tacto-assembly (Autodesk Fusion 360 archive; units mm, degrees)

design "smart-kitchen-timer" references "3.7v li-ion 500mah Battery", "Micro_Button_6x6", "XIAO-nRF52840 v15", "HW-040 Encoder module", "Wavehsare 1.54in e-paper - Module"
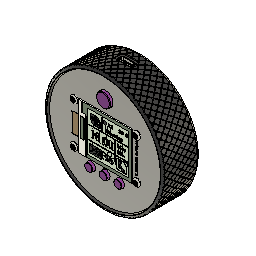
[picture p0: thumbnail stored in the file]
part number: 2025-10-14-07-23-40-648
part number: 2025-10-14-07-30-10-899
part number: 2025-10-14-07-51-40-944
part number: 2025-10-14-07-53-39-691
part number: 2025-10-14-09-25-19-943
part number: 2025-10-14-09-45-08-360
sketch "Skizze1" plane through (0, 0, 0) normal (0, 1, 0) x axis (1, 0, 0)
  circle C1 centre (0, 0) radius 40
  point P1 (0, 0)
  point P2 (0, 0)
  coincident P1 P2
  dimension "d1" diameter C1 = 80
component_insert "Komponente einfügen1"
component_insert "Komponente einfügen1"
sketch "Skizze2" plane through (0, 0, 0) normal (1, 0, 0) x axis (0, 1, 0)
  line L1 (23, 41) -> (-2, 41)
  line L2 (23, 39) -> (23, 41)
  line L3 (-2, 39) -> (23, 39)
  line L4 (-2, 41) -> (-2, 39)
  point P6 (0, 0)
  horizontal L1
  vertical L2
  horizontal L3
  vertical L4
  dimension "d2" distance L4 P6 = 2
  dimension "d3" distance L1 L3 = 2
  dimension "d4" distance L2 L4 = 25
  dimension "d5" distance L3 P6 = 39 (= "( 78 / 2 ) * 1 mm")
revolve "Drehen1" sketch "Skizze2" AlongAngle 360
sketch "Skizze3" plane through (0, 23, 0) normal (0, 1, 0) x axis (-1, 0, 0)
  circle C1 centre (0, 0) radius 41
  circle C2 centre (0, 0) radius 39
position "Position1"
copy_paste "Kopieren/Einfügen1"
copy_paste "Kopieren/Einfügen2"
position "Position2"
sketch "Skizze4" plane through (0, 0, 0) normal (0, -1, 0) x axis (1, 0, 0)
  line L1 (-24.0928, 9.2469) -> (-24.0928, 13.5382)
  line L2 (-22.6392, 6.9253) -> (-23.479, 7.7651)
  line L3 (-22.0255, -4.834) -> (-22.0255, 5.4436)
  line L4 (-23.479, -7.1555) -> (-22.6392, -6.3157)
  line L5 (-24.0928, -12.9286) -> (-24.0928, -8.6373)
  line L6 (20.7255, -16.4211) -> (-20.6003, -16.4211)
  line L7 (24.218, 13.5382) -> (24.218, -12.9286)
  line L8 (-20.6003, 17.0307) -> (20.7255, 17.0307)
  curve K1 (22.0151, 11.4392) -> (21.1308, 11.7999)
  line L9 (22.0151, 10.9505) -> (22.0151, 11.4392)
  line L10 (20.748, 10.9505) -> (22.0151, 10.9505)
  line L11 (20.748, 11.4054) -> (20.748, 10.9505)
  line L12 (20.9551, 11.4054) -> (20.748, 11.4054)
  curve K2 (20.7864, 11.95) -> (20.9551, 11.4054)
  line L13 (21.1308, 11.7999) -> (20.7864, 11.95)
  curve K3 (21.6416, 10.2139) -> (21.5008, 9.7473)
  line L14 (21.6847, 10.6921) -> (21.6416, 10.2139)
  curve K4 (21.5008, 10.7212) -> (21.6847, 10.6921)
  line L15 (21.5008, 9.7473) -> (21.5008, 10.7212)
  curve K5 (21.893, 8.1706) -> (20.9353, 8.1345)
  line L16 (22.4957, 8.1706) -> (21.893, 8.1706)
  line L17 (22.4957, 7.6807) -> (22.4957, 8.1706)
  line L18 (20.748, 7.6807) -> (22.4957, 7.6807)
  line L19 (20.748, 8.1345) -> (20.748, 7.6807)
  line L20 (20.9353, 8.1345) -> (20.748, 8.1345)
  curve K6 (21.1715, 6.9127) -> (21.8616, 6.9407)
  curve K7 (21.1599, 6.4927) -> (21.1715, 6.9127)
  line L21 (21.1099, 6.0284) -> (21.1599, 6.4927)
  curve K8 (22.0151, 7.448) -> (21.1099, 6.0284)
  line L22 (22.0151, 6.9919) -> (22.0151, 7.448)
  line L23 (22.0151, 4.8578) -> (21.367, 4.8578)
  line L24 (22.0151, 4.3144) -> (22.0151, 4.8578)
  line L25 (20.2662, 4.3144) -> (22.0151, 4.3144)
  curve K9 (21.367, 4.8578) -> (20.2662, 4.3144)
  line L26 (21.566, 4.0817) -> (21.189, 4.0817)
  line L27 (21.566, 3.3753) -> (21.566, 4.0817)
  line L28 (21.189, 3.3753) -> (21.566, 3.3753)
  line L29 (21.189, 4.0817) -> (21.189, 3.3753)
  curve K10 (21.6416, 2.7377) -> (21.5008, 2.2699)
  line L30 (21.6847, 3.2159) -> (21.6416, 2.7377)
  curve K11 (21.5008, 3.245) -> (21.6847, 3.2159)
  line L31 (21.5008, 2.2699) -> (21.5008, 3.245)
  curve K12 (22.0151, -0.1213) -> (22.0151, 0.2406)
  line L32 (22.0151, -0.6077) -> (22.0151, -0.1213)
  line L33 (20.2662, -0.6077) -> (22.0151, -0.6077)
  line L34 (20.2662, -0.1213) -> (20.2662, -0.6077)
  line L35 (20.9097, -0.1213) -> (20.2662, -0.1213)
  curve K13 (22.0151, 0.7293) -> (20.9097, -0.1213)
  line L36 (22.0151, 0.2406) -> (22.0151, 0.7293)
  curve K14 (21.1529, -0.8579) -> (21.5695, -0.8323)
  line L37 (21.2146, -1.314) -> (21.1529, -0.8579)
  curve K15 (21.5183, -1.2966) -> (21.2146, -1.314)
  line L38 (21.5695, -0.8323) -> (21.5183, -1.2966)
  curve K16 (22.0151, -3.3841) -> (22.0151, -3.021)
  line L39 (22.0151, -3.8693) -> (22.0151, -3.3841)
  line L40 (20.748, -3.8693) -> (22.0151, -3.8693)
  line L41 (20.748, -3.4167) -> (20.748, -3.8693)
  line L42 (20.9539, -3.4167) -> (20.748, -3.4167)
  curve K17 (22.0151, -2.5323) -> (20.9539, -3.4167)
  line L43 (22.0151, -3.021) -> (22.0151, -2.5323)
  line L44 (22.0151, -4.1846) -> (20.748, -4.1846)
  line L45 (22.0151, -4.6699) -> (22.0151, -4.1846)
  line L46 (20.748, -4.6699) -> (22.0151, -4.6699)
  line L47 (20.748, -4.1846) -> (20.748, -4.6699)
  line L48 (20.5955, -4.1846) -> (20.2662, -4.1846)
  line L49 (20.5955, -4.6699) -> (20.5955, -4.1846)
  line L50 (20.2662, -4.6699) -> (20.5955, -4.6699)
  line L51 (20.2662, -4.1846) -> (20.2662, -4.6699)
  line L52 (20.7072, -10.346) -> (21.1029, -10.346)
  curve K18 (20.2371, -9.7444) -> (20.7072, -10.346)
  line L53 (20.2371, -9.3418) -> (20.2371, -9.7444)
  line L54 (22.0151, -9.3418) -> (20.2371, -9.3418)
  line L55 (22.0151, -9.8352) -> (22.0151, -9.3418)
  line L56 (20.8504, -9.8352) -> (22.0151, -9.8352)
  curve K19 (21.1029, -10.346) -> (20.8504, -9.8352)
  line L57 (22.0151, -8.2468) -> (21.5299, -8.2468)
  line L58 (22.0151, -8.7658) -> (22.0151, -8.2468)
  line L59 (21.5299, -8.7658) -> (22.0151, -8.7658)
  line L60 (21.5299, -8.2468) -> (21.5299, -8.7658)
  curve K20 (21.2635, -7.5428) -> (21.5043, -7.5265)
  line L61 (21.2041, -7.9571) -> (21.2635, -7.5428)
  line L62 (20.2662, -7.8012) -> (21.2041, -7.9571)
  line L63 (20.2662, -6.6457) -> (20.2662, -7.8012)
  line L64 (20.6537, -6.6457) -> (20.2662, -6.6457)
  line L65 (20.6537, -7.4288) -> (20.6537, -6.6457)
  line L66 (20.9144, -7.4719) -> (20.6537, -7.4288)
  curve K21 (21.5578, -8.0188) -> (20.9144, -7.4719)
  line L67 (21.5043, -7.5265) -> (21.5578, -8.0188)
  line L68 (22.0151, -5.1051) -> (21.6893, -5.1051)
  line L69 (22.0151, -5.5286) -> (22.0151, -5.1051)
  line L70 (21.6893, -5.5286) -> (22.0151, -5.5286)
  line L71 (21.6893, -6.4165) -> (21.6893, -5.5286)
  line L72 (21.2891, -6.4165) -> (21.6893, -6.4165)
  line L73 (20.2371, -5.5286) -> (21.2891, -6.4165)
  line L74 (20.2371, -5.1051) -> (20.2371, -5.5286)
  line L75 (21.3123, -5.1051) -> (20.2371, -5.1051)
  line L76 (21.3123, -4.884) -> (21.3123, -5.1051)
  line L77 (21.6893, -4.884) -> (21.3123, -4.884)
  line L78 (21.6893, -5.1051) -> (21.6893, -4.884)
  line L79 (18.489, 16.2631) -> (-18.511, 16.2631)
  line L80 (18.489, -16.2369) -> (18.489, 16.2631)
  line L81 (-18.511, -16.2369) -> (18.489, -16.2369)
  line L82 (-18.511, 16.2631) -> (-18.511, -16.2369)
  arc A1 centre (-21.9973, 9.2469) radius 2.0955 clockwise from (-23.479, 7.7651) to (-24.0928, 9.2469)
  arc A2 centre (-24.121, 5.4436) radius 2.0955 clockwise from (-22.6392, 6.9253) to (-22.0255, 5.4436)
  arc A3 centre (-24.121, -4.834) radius 2.0955 clockwise from (-22.0255, -4.834) to (-22.6392, -6.3157)
  arc A4 centre (-21.9973, -8.6373) radius 2.0955 clockwise from (-24.0928, -8.6373) to (-23.479, -7.1555)
  arc A5 centre (-20.6003, -12.9286) radius 3.4925 clockwise from (-20.6003, -16.4211) to (-24.0928, -12.9286)
  arc A6 centre (20.7255, -12.9286) radius 3.4925 clockwise from (24.218, -12.9286) to (20.7255, -16.4211)
  arc A7 centre (20.7255, 13.5382) radius 3.4925 clockwise from (20.7255, 17.0307) to (24.218, 13.5382)
  arc A8 centre (-20.6003, 13.5382) radius 3.4925 clockwise from (-24.0928, 13.5382) to (-20.6003, 17.0307)
  circle C1 centre (-21.5928, 14.0789) radius 1.0795
  circle C2 centre (21.4072, 14.0789) radius 1.0795
  circle C3 centre (21.4072, -13.9211) radius 1.0795
  circle C4 centre (-21.5928, -13.9211) radius 1.0795
  arc A9 centre (21.8316, 7.2866) radius 0.3472 clockwise from (22.0151, 6.9919) to (21.8616, 6.9407)
  circle C5 centre (0, 0) radius 38.5
  circle C6 centre (-21.5928, 14.0789) radius 1.65
  circle C7 centre (-21.5928, -13.9211) radius 1.65
  circle C8 centre (21.5416, -13.9211) radius 1.65
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  point P1 (0, 0)
  point P128 (0, 0)
  point P123 (-18.511, 16.2631)
  point P126 (-18.511, -16.2369)
  point P124 (18.489, 16.2631)
  point P127 (-18.161, 15.9131)
  point P131 (21.5416, -13.9211)
  point P132 (21.4072, 14.0789)
  point P129 (-21.5928, 14.0789)
  point P133 (-10, -20)
  point P134 (0, -20)
  point P135 (10, -20)
  point P136 (0, 25)
  horizontal L79
  vertical L80
  horizontal L81
  vertical L82
  coincident P1 P128
  concentric C1 C6
  concentric C4 C7
  dimension "d8" distance P123 P126 = 32.5
  dimension "d9" distance P123 P124 = 37
  dimension "d10" distance P123 P127 = 0.35
  dimension "d11" distance P123 P127 = 0.35
  dimension "d12" diameter C5 = 77
  dimension "d15" diameter C6 = 3.3
  dimension "d16" diameter C7 = 3.3
  dimension "d17" diameter C8 = 3.3
  dimension "d18" diameter = 3.3
  dimension "d19" distance P131 P132 = 28 (= "33 mm - 5 mm")
  dimension "d20" distance P129 P132 = 43 (= "48 mm - 5 mm")
  dimension "d36" distance P133 P134 = 10
  dimension "d37" distance P134 P135 = 10
  dimension "d38" distance P1 P133 = 20
  dimension "d39" distance P1 P133 = 10
  dimension "d40" diameter = 6
  dimension "d41" diameter = 6
  dimension "d42" diameter = 6
  dimension "d43" diameter = 10
  dimension "d97" distance P1 P136 = 25
  dimension "d99" distance P133 P136 = 10
extrude "Extrusion1" new body sketch "Skizze4" along normal blind 0.5766
chamfer "Fase" distance 1 Rotate Angle 60
sketch "Skizze4" plane through (0, 23, 0) normal (0, 1, 0) x axis (-1, 0, 0)
coil_primitive "Grundkörper Spirale" Diameter 82 SectionSize 1 TaperAngle 0 Revolutions 0.1 Height -30
mirror "Spiegeln" mirrorStitchTolerance 0.1
circular_pattern "C-Anordnung" countU 60 TotalAngle 360
sketch "Skizze3" plane through (0, 0, 0) normal (0, 0, 1) x axis (1, 0, 0)
sketch "Skizze2" plane through (0, 0, 0) normal (0, 0, 1) x axis (1, 0, 0)
  line L1 (-2.5048, -15) -> (-1.8562, -15)
  line L2 (-2.7, -17.7793) -> (-2.7, -15.25)
  line L3 (-1.7, -18) -> (-2.45, -18)
  line L4 (-1.7, -15.2) -> (-1.7, -16.2)
  line L5 (0, -16.2) -> (-1.7, -16.2)
  line L6 (0, -18) -> (0, -16.2)
  line L7 (-1.7, -18) -> (0, -18)
  line L8 (-2.7, -17.7793) -> (-2.45, -18)
  line L9 (-2.5048, -15) -> (-2.7, -15.25)
  line L10 (-1.8562, -15) -> (-1.7, -15.2)
  point P4 (-2.7, -18)
  point P3 (-2.7, -15)
  point P2 (-1.7, -15)
  point P6 (0, 0)
  point P10 (-2.45, -18)
  point P12 (-2.7, -15.25)
  point P14 (-1.7, -15.2)
  horizontal L1
  vertical L2
  horizontal L3
  vertical L4
  perpendicular L4 L5
  perpendicular L5 L6
  coincident P4 L3
  coincident P4 L2
  coincident P3 L2
  coincident P3 L1
  coincident P2 L4
  coincident P2 L1
  dimension "d44" distance L4 P6 = 1.7 (= "( 3.4 / 2 ) * 1 mm")
  dimension "d45" distance P3 P4 = 3
  dimension "d47" distance P2 P3 = 1
  dimension "d48" distance L1 P6 = 15
  dimension "d49" distance L5 L7 = 1.8
  dimension "d51" distance P4 P10 = 0.25
  dimension "d52" angle L3 L8 = 41.437
  dimension "d53" distance P3 P12 = 0.25
  dimension "d54" angle L2 L9 = 37.982
  dimension "d55" distance P2 P14 = 0.2
  dimension "d56" angle L4 L10 = 37.982
  dimension "d57" distance L2 L6 = 2.7
revolve "Drehen1" sketch "Skizze2" AlongAngle 360
ground "Fixieren1"
ground "Fixieren2"
ground "Fixieren3"
step "Geometrische Beziehung1" Offset 0 Offset 0
copy_paste "Kopieren/Einfügen3"
step "Geometrische Beziehung2" Offset 0 Offset 0
copy_paste "Kopieren/Einfügen4"
step "Geometrische Beziehung3" Offset 0 Offset 0
copy_paste "Kopieren/Einfügen5"
ground "Fixieren4"
sketch "Skizze1" plane through (0, 0, 0) normal (0, 0, 1) x axis (1, 0, 0)
  line L1 (4.0625, -21) -> (2, -21)
  line L2 (4.75, -23.5803) -> (4.75, -21.6875)
  line L3 (3.0711, -24) -> (4.3303, -24)
  line L4 (1.7, -21.3) -> (1.7, -22.2)
  line L5 (0, -24) -> (3.0711, -24)
  line L6 (0, -22.2) -> (0, -24)
  line L7 (1.7, -22.2) -> (0, -22.2)
  line L8 (1.7, -21.3) -> (2, -21)
  line L9 (4.0625, -21) -> (4.75, -21.6875)
  line L10 (4.3303, -24) -> (4.75, -23.5803)
  point P1 (0, 0)
  point P6 (0, -24)
  point P2 (1.7, -21)
  point P3 (4.75, -21)
  point P4 (4.75, -24)
  point P9 (2, -21)
  point P10 (1.7, -21.3)
  point P11 (4.75, -21.6875)
  point P12 (4.0625, -21)
  point P13 (4.75, -23.5803)
  point P14 (4.3303, -24)
  horizontal L1
  vertical L2
  horizontal L3
  vertical L4
  perpendicular L4 L5
  perpendicular L5 L6
  perpendicular L4 L7
  vertical P1 P6
  coincident P2 L1
  coincident P2 L4
  coincident P3 L2
  coincident P3 L1
  coincident P4 L2
  coincident P4 L3
  dimension "d64" distance L4 L6 = 1.7 (= "( 3.4 / 2 ) * 1 mm")
  dimension "d65" distance L1 L3 = 3
  dimension "d66" distance L5 L7 = 1.8
  dimension "d67" distance L2 L6 = 4.75 (= "( 9.5 / 2 ) * 1 mm")
  dimension "d68" distance P1 L1 = 21
  dimension "d70" distance P2 P9 = 0.3
  dimension "d71" distance P2 P10 = 0.3 (= "d70")
  dimension "d72" distance P3 P11 = 0.6875
  dimension "d73" distance P3 P12 = 0.6875 (= "d72")
  dimension "d74" distance P4 P13 = 0.4197
  dimension "d75" distance P4 P14 = 0.4197 (= "d74")
revolve "Drehen1" sketch "Skizze1" AlongAngle 360
step "Geometrische Beziehung4" Offset 0 Offset 0
component_insert "Komponente einfügen1"
position "Position3"
sketch "Skizze5" plane through (0, 0, 0) normal (0, 0, 1) x axis (1, 0, 0)
  line L1 (4, 16) -> (-4, 16)
  line L2 (5, 13) -> (5, 15)
  line L3 (-4, 12) -> (4, 12)
  line L4 (-5, 15) -> (-5, 13)
  line L5 (-4, 10.7498) -> (4, 10.7498)
  line L6 (6.2502, 13) -> (6.2502, 15)
  line L7 (4, 17.2502) -> (-4, 17.2502)
  line L8 (-6.2502, 15) -> (-6.2502, 13)
  arc A1 centre (4, 13) radius 1 clockwise from (5, 13) to (4, 12)
  arc A2 centre (4, 15) radius 1 clockwise from (4, 16) to (5, 15)
  arc A3 centre (-4, 15) radius 1 clockwise from (-5, 15) to (-4, 16)
  arc A4 centre (-4, 13) radius 1 clockwise from (-4, 12) to (-5, 13)
  arc A5 centre (-4, 13) radius 2.2502 clockwise from (-4, 10.7498) to (-6.2502, 13)
  arc A6 centre (4, 13) radius 2.2502 clockwise from (6.2502, 13) to (4, 10.7498)
  arc A7 centre (4, 15) radius 2.2502 clockwise from (4, 17.2502) to (6.2502, 15)
  arc A8 centre (-4, 15) radius 2.2502 clockwise from (-6.2502, 15) to (-4, 17.2502)
  point P2 (5, 12)
  point P3 (-5, 12)
  point P4 (0, 0)
  horizontal L1
  vertical L2
  horizontal L3
  vertical L4
  coincident P2 L3
  coincident P2 L2
  tangent L3 A1
  tangent L2 A1
  tangent L2 A2
  tangent L1 A2
  equal A1 A2
  tangent L4 A3
  tangent L1 A3
  equal A1 A3
  coincident P3 L3
  coincident P3 L4
  tangent L3 A4
  tangent L4 A4
  equal A1 A4
  dimension "d78" distance P2 P3 = 10
  dimension "d79" distance L3 P4 = 12
  dimension "d80" distance L2 P4 = 5
  dimension "d81" distance L1 L3 = 4
  dimension "d82" radius A1 = 1
  dimension "d85" = -1.2502
extrude "Extrusion1" cut sketch "Skizze5" profile of L1 L2 L3 L4 A1 A2 A3 A4 along normal blind 46
extrude "Extrusion2" cut sketch "Skizze5" blind 8 from offset 40
sketch "Skizze7" plane through (0, 23, 0) normal (0, 1, 0) x axis (-1, 0, 0)
  line L1 (-39, -0.0019) -> (39, -0.0019)
  line L2 (0, 39) -> (0, -39)
  line L3 (2, 38.9487) -> (2, -38.9487)
  line L4 (-2, 38.9487) -> (-2, -38.9487)
  line L5 (-38.9488, 1.9981) -> (38.9488, 1.9981)
  line L6 (-38.9486, -2.0019) -> (38.9486, -2.0019)
  circle C1 centre (0, 0) radius 39
  circle C2 centre (0, 0) radius 40
  circle C3 centre (0, 0) radius 6
  point P3 (39, -0.0019)
  point P4 (-39, -0.0019)
  point P5 (0, -39)
  point P6 (0, 39)
  point P13 (38.9486, -2.0019)
  point P11 (38.9488, 1.9981)
  point P7 (2, -38.9487)
  point P9 (-2, -38.9487)
  point P14 (-38.9486, -2.0019)
  point P12 (-38.9488, 1.9981)
  point P10 (-2, 38.9487)
  point P8 (2, 38.9487)
  point P1 (0, 0)
  point P15 (0, 0)
  coincident C1 P3
  coincident C1 P4
  horizontal L1
  coincident C1 P5
  coincident C1 P6
  perpendicular L1 L2
  coincident C1 P13
  coincident C1 P11
  coincident C1 P7
  coincident C1 P9
  coincident C1 P14
  coincident C1 P12
  coincident C1 P10
  coincident C1 P8
  coincident P1 P15
  dimension "d89" = 2
  dimension "d90" = -2
  dimension "d91" = 2
  dimension "d92" = -2
  dimension "d96" diameter C3 = 12
extrude "Extrusion3" add sketch "Skizze7" profile of C1 L1 L2 L3 L4 L5 L6 C3 against normal blind 2
component_insert "Komponente einfügen2"
component_insert "Komponente einfügen3"
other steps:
create_component "Komponente erstellen1"
create_component "Komponente erstellen2"
create_component "Komponente erstellen3"
create_component "Komponente erstellen5"
create_component "Komponente erstellen6"

design "Micro_Button_6x6"
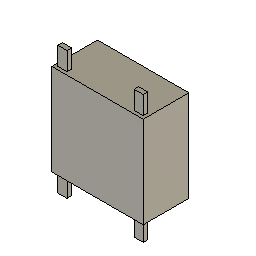
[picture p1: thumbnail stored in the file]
description: STEP AP203
part number: Micro_Button_6x6
base_feature "Base Feature"

design "3.7v li-ion 500mah Battery"
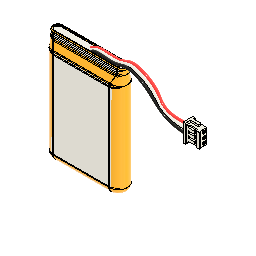
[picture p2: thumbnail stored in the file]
description: Part Number
part number: Battery
base_feature "Base Feature"

design "HW-040 Encoder module"
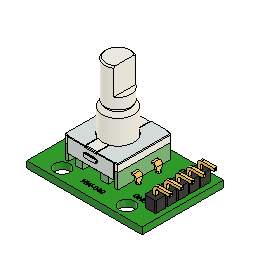
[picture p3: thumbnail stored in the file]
description: Unknown
part number: HW-040 Encoder module
description: Encoder PCB
part number: Encoder PCB
description: Knob static part
part number: Knob static part
description: Knob rotary part
part number: Knob rotary part
description: Top plate knob
part number: Top plate knob
description: Plastic bottom knob
part number: Plastic bottom knob
description: Encoder terminal
part number: Encoder terminal
description: Encoder body
part number: Encoder body
description: 1X5 Pin Socket
part number: 1X5 Pin Socket
description: Bend pin
part number: Bend pin
base_feature "Base Feature1"
base_feature "Base Feature1"
base_feature "Base Feature1"
base_feature "Base Feature1"
base_feature "Base Feature1"
base_feature "Base Feature1"
base_feature "Base Feature1"
base_feature "Base Feature1"
base_feature "Base Feature1"
base_feature "Base Feature1"
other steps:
create_component "CreateComponent1"
create_component "CreateComponent2"
create_component "CreateComponent1"
create_component "CreateComponent2"
create_component "CreateComponent3"
create_component "CreateComponent4"
create_component "CreateComponent5"
create_component "CreateComponent3"
create_component "CreateComponent1"
create_component "CreateComponent2"
create_component "CreateComponent4"
create_component "CreateComponent1"
create_component "CreateComponent2"

design "XIAO-nRF52840 v15"
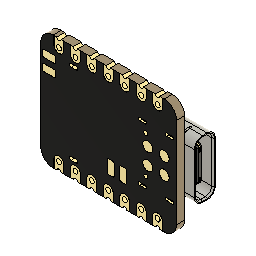
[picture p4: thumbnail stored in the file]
description: Part Number
part number: XIAO-nRF52840
part number: BOSS-EXTRUDE14_8_
part number: BOSS-EXTRUDE7_4_
part number: BOSS-EXTRUDE7_3_
part number: BOSS-EXTRUDE14_4_
part number: BOSS-EXTRUDE14_2_
part number: BOSS-EXTRUDE14_11_
part number: BOSS-EXTRUDE7_7_
part number: BOSS-EXTRUDE14_9_
part number: BOSS-EXTRUDE14_3_
part number: BOSS-EXTRUDE14_7_
part number: MIRROR2
part number: BOSS-EXTRUDE14_5_
part number: BOSS-EXTRUDE14_12_
part number: BOSS-EXTRUDE7_8_
part number: BOSS-EXTRUDE7_1_
part number: BOSS-EXTRUDE14_10_
part number: BOSS-EXTRUDE7_9_
part number: BOSS-EXTRUDE14_6_
base_feature "Base Feature1"
base_feature "Base Feature1"
base_feature "Base Feature1"
base_feature "Base Feature1"
base_feature "Base Feature1"
base_feature "Base Feature1"
base_feature "Base Feature1"
base_feature "Base Feature1"
base_feature "Base Feature1"
base_feature "Base Feature1"
base_feature "Base Feature1"
base_feature "Base Feature1"
base_feature "Base Feature1"
base_feature "Base Feature1"
base_feature "Base Feature1"
base_feature "Base Feature1"
base_feature "Base Feature1"
base_feature "Base Feature1"
base_feature "Base Feature1"
base_feature "Base Feature1"
base_feature "Base Feature1"
base_feature "Base Feature1"
base_feature "Base Feature1"
base_feature "Base Feature1"
base_feature "Base Feature1"
base_feature "Base Feature1"
base_feature "Base Feature1"
base_feature "Base Feature1"
base_feature "Base Feature1"
base_feature "Base Feature1"
base_feature "Base Feature1"
base_feature "Base Feature1"
base_feature "Base Feature1"
base_feature "Base Feature1"
base_feature "Base Feature1"
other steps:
create_component "CreateComponent1"
create_component "CreateComponent1"
create_component "CreateComponent1"
create_component "CreateComponent2"
create_component "CreateComponent3"
create_component "CreateComponent4"
create_component "CreateComponent5"
create_component "CreateComponent6"
create_component "CreateComponent7"
create_component "CreateComponent8"
create_component "CreateComponent9"
create_component "CreateComponent10"
create_component "CreateComponent11"
create_component "CreateComponent12"
create_component "CreateComponent13"
create_component "CreateComponent14"
create_component "CreateComponent15"
create_component "CreateComponent16"
create_component "CreateComponent17"
create_component "CreateComponent18"
create_component "CreateComponent19"
create_component "CreateComponent20"
create_component "CreateComponent21"
create_component "CreateComponent22"
create_component "CreateComponent23"
create_component "CreateComponent24"
create_component "CreateComponent2"
create_component "CreateComponent3"
create_component "CreateComponent1"
create_component "CreateComponent2"
create_component "CreateComponent4"
create_component "CreateComponent1"
create_component "CreateComponent2"
create_component "CreateComponent3"
create_component "CreateComponent4"
create_component "CreateComponent5"
create_component "CreateComponent6"
create_component "CreateComponent5"

design "Wavehsare 1.54in e-paper - Module"
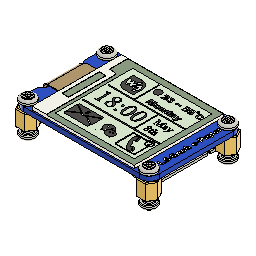
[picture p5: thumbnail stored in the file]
description: Unknown
part number: Wavehsare 1.54in e-paper - Module
description: Waveshare 1.54 E ink - Display Folded
part number: Waveshare 1.54 E ink - Display Folded
description: 524352433
part number: 524352433
description: 0603 Capacitor
part number: 0603 Capacitor
description: CD32
part number: CD32
description: Board
part number: Board
description: 0603 Resistor
part number: 0603 Resistor
description: SOT-23
part number: SOT-23
description: Diode (SOD-323)
part number: Diode (SOD-323)
description: JST XH 8 S8B-XH-A1 shrouded header connector v4
part number: JST XH 8 S8B-XH-A1 shrouded header connector v4
base_feature "Base Feature1"
base_feature "Base Feature1"
base_feature "Base Feature1"
base_feature "Base Feature1"
base_feature "Base Feature1"
base_feature "Base Feature1"
base_feature "Base Feature1"
base_feature "Base Feature1"
base_feature "Base Feature1"
base_feature "Base Feature1"
base_feature "Base Feature1"
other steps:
create_component "CreateComponent1"
create_component "CreateComponent2"
create_component "CreateComponent3"
create_component "CreateComponent4"
create_component "CreateComponent5"
create_component "CreateComponent6"
create_component "CreateComponent7"
create_component "CreateComponent8"
create_component "CreateComponent9"
create_component "CreateComponent10"
create_component "CreateComponent11"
